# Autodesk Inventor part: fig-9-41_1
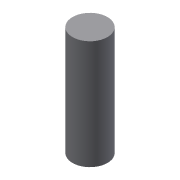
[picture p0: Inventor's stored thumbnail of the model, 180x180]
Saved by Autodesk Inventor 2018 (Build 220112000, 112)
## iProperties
Created: 2013-03
Part Number: fig-9-41_1
Material: Generic
Document SubType Name: Modeling
Designer: CADCIM
Density: 1 g/cm^3
Appearance: Default
Author: CADCIM
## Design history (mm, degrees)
sketch "Sketch1"
  geometry: C1 r 4 at (0, 0); 1 further point
  constraints: 1 centre point, 1 coincident
  dimensions: "d0" = 8 diameter of C1
extrude "Extrusion1" new body sketch "Sketch1" stored distance "d2" = 25; taper "d3" = 0 deg
body "Solid1"
